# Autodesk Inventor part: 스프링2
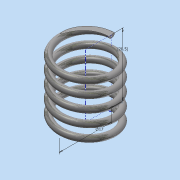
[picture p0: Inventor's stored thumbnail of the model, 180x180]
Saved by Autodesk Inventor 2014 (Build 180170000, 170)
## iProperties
Created: 2016-03
Part Number: 스프링2
Material: 스테인레스 스틸
Document SubType Name: Modeling
Designer: SCD-A13
Density: 8.08 g/cm^3
Appearance: 반연마
Mass: 6.63802 g
Surface Area: 16.7216 cm^2
Volume: 0.821537 cm^3
Author: SCD-A13
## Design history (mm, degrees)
sketch "스케치1"
  geometry: L1 (0, 20.5)-(8.5, 20.5); L2 (8.5, 20.5)-(8.5, 0); L3 (8.5, 0)-(0, 0); L4 (0, 0)-(0, 20.5); C1 r 1 at (8.5, 0); 1 further point
  constraints: 8 end point, 2 coincident, 2 parallel, 1 centre point, 1 horizontal, 1 perpendicular
  dimensions: "d0" = 2 diameter of C1; "d1" = 17 diameter of L2 L4; "d2" = 20.5 distance between parallel lines of L1 L3 (derived)
feature "코일1" pitch "d3" = 10; turns "d5" = 5; dims "d4" = 20.5 (= d2), "d6" = 0, angle "d7" = 90 deg, angle "d8" = 90 deg, "d9" = 0, "d10" = 0
node "작업 평면1"
sketch "스케치2"
  geometry: L1 (1, 0)-(-1, 0) reference; 1 further point
  constraints: 1 horizontal alignment
extrude "돌출1" cut sketch "스케치2" stored distance "d12" = 10; taper "d13" = 0 deg
node "작업 평면2"
sketch "스케치3"
  geometry: L1 (9.5, 0)-(7.5, 0) reference; 1 further point
  constraints: 1 horizontal alignment
extrude "돌출2" cut sketch "스케치3" stored distance "d15" = 10; taper "d16" = 0 deg
node "솔리드1"
node "절단 모서리 투영1"
node "절단 모서리 투영2"
other parameters: "d11" = 0, "d14" = 0
